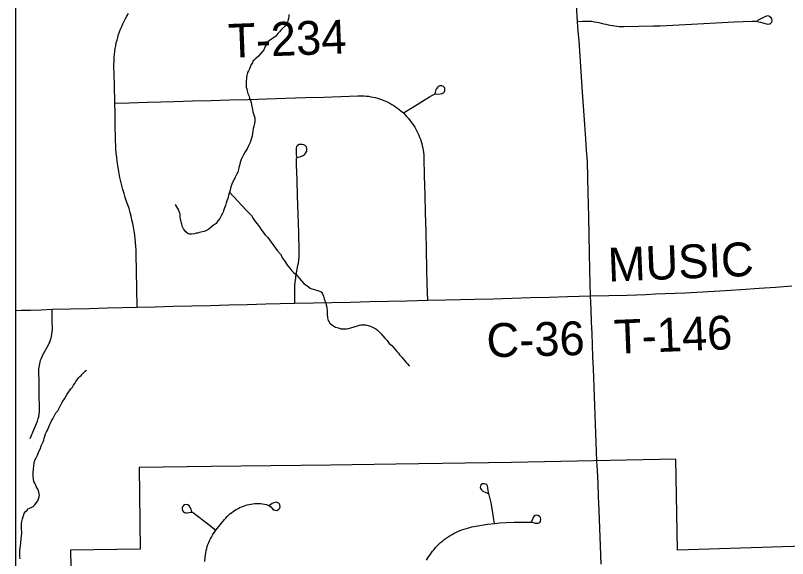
# Model space of a CAD drawing. Extents: x 103424 to 286016, y 38711 to 110967.
# Drawn here: x 103424 to 110306, y 48305 to 53149 of the extents above; entities that cross this region are included whole.
import ezdxf

# ---------------------------------------------------------------- set-up
doc = ezdxf.new("R2010")
doc.units = 0
for name, color, linetype in [('GM_X_City_Street', 7, 'Continuous'), ('GM_X_Corporation', 7, 'Continuous'), ('GM_X_County_Road_Text', 7, 'Continuous'), ('GM_X_Minor_River', 7, 'Continuous'), ('GM_X_State_Route', 7, 'Continuous'), ('GM_X_Township_Road', 7, 'Continuous'), ('GM_X_Township_Road_Text', 7, 'Continuous')]:
    doc.layers.add(name, color=color, linetype=linetype)

msp = doc.modelspace()

# ---------------------------------------------------------------- linework, layer by layer
at = {"layer": 'GM_X_City_Street'}
for points in [[(107692.3, 48618.7), (107685.6, 48672.4), (107676.2, 48734.3), (107664.8, 48802.2), (107649.9, 48861.2), (107637.5, 48910.2), (107633.7, 48937.3), (107630.2, 48951.9), (107624.2, 48962.1), (107615.1, 48968.2), (107602.4, 48971.2), (107587.9, 48970.6), (107573.3, 48961.5), (107567.9, 48951.2), (107566.7, 48939.8), (107569.7, 48929.5), (107576.4, 48917), (107589.1, 48907.1), (107604, 48899.7), (107638.2, 48886.1)], [(105113, 48278.3), (105114.5, 48316.9), (105116.3, 48332.3), (105120.3, 48359), (105124.1, 48377.1), (105128.4, 48394.9), (105133.7, 48412.6), (105139.5, 48430.1), (105146, 48447.2), (105153.3, 48464.1), (105161.4, 48480.6), (105170, 48496.9), (105179.3, 48512.7), (105189.4, 48528.2), (105199.9, 48543.2), (105211.3, 48557.8), (105287.1, 48652.4), (105298.2, 48665.7), (105310.3, 48678.6), (105322.6, 48690.9), (105335.4, 48702.7), (105349, 48713.8), (105362.9, 48724.3), (105377.5, 48734.1), (105392.3, 48743.3), (105407.5, 48751.8), (105423.1, 48759.6), (105439.2, 48766.6), (105455.3, 48772.9), (105471.9, 48778.5), (105488.8, 48783.3), (105505.6, 48787.3), (105522.7, 48790.6), (105540.1, 48793), (105557.5, 48794.7), (105574.9, 48795.6), (105609.6, 48795), (105627, 48793.5), (105644.3, 48791.2), (105661.5, 48788.1), (105683.6, 48777.6), (105699.8, 48765.9), (105714.9, 48749.3), (105726.2, 48739.9), (105736.3, 48735.4), (105747.7, 48733.7), (105760.8, 48737.7), (105772.2, 48744.8), (105780.4, 48755.7), (105783.9, 48769.2), (105780.8, 48783.6), (105774, 48795.3), (105763.9, 48802.9), (105751.4, 48806.6), (105725.4, 48802.5), (105712.2, 48794.6), (105688.9, 48779.1)], [(104995.6, 48722.3), (104986.1, 48750.4), (104980.6, 48764), (104972.4, 48775.4), (104960.2, 48784), (104943.3, 48785.6), (104931.5, 48782.9), (104921.4, 48776.9), (104913.1, 48767.1), (104909.3, 48756.9), (104909.7, 48744.9), (104913.8, 48733.2), (104921, 48722.6), (104930.8, 48715.5), (104942.5, 48712.1), (104954.2, 48711.3), (104971.5, 48716.3), (104985.8, 48719.3), (104997.9, 48718.5), (105010.7, 48712.5), (105037.8, 48692.9), (105124.5, 48625.4), (105211.3, 48557.8)], [(107088.5, 48291.6), (107104.8, 48318.8), (107116.4, 48336.4), (107128.5, 48353.6), (107141.4, 48370.3), (107154.7, 48386.7), (107168.5, 48402.5), (107183.2, 48417.8), (107198, 48432.6), (107213.6, 48446.9), (107229.7, 48460.6), (107246.1, 48473.8), (107263, 48486.4), (107280.4, 48498.3), (107298.2, 48509.7), (107316.4, 48520.5), (107334.8, 48530.6), (107353.6, 48540), (107372.8, 48548.8), (107392.4, 48556.9), (107412, 48564.3), (107431.9, 48571.1), (107452.3, 48577.1), (107472.7, 48582.4), (107493.1, 48587), (107527.6, 48593.9), (107562.3, 48600), (107597.1, 48605.6), (107631.8, 48610.5), (107692.3, 48618.7), (107742.5, 48624.1), (107798.8, 48627.5), (107867.8, 48628.8), (107943.5, 48630.1), (108030, 48628.1), (108054.9, 48622), (108068.9, 48619.3), (108084.2, 48620.3), (108097.8, 48627.5), (108103.9, 48635.6), (108107.3, 48653), (108102.5, 48670), (108094.7, 48680.9), (108080.8, 48689.1), (108067.4, 48690.5), (108055, 48687.5), (108045.2, 48681.1), (108038, 48670.5), (108032, 48654.7), (108020.7, 48631.7)]]:
    msp.add_lwpolyline(points, dxfattribs=at)
at = {"layer": 'GM_X_Corporation'}
msp.add_lwpolyline([(103423.7, 96534.8), (103423.7, 38711.2), (175679.7, 38711.2), (175679.7, 110967.2), (119699, 110967.2), (119716.9, 106542.5), (119719.8, 106322.8), (119720.8, 106006.3), (119709.7, 99445.7), (119706.4, 99064.2), (119663.9, 96690), (117026.4, 96688.2), (115542.1, 96665), (105081.7, 96574.5)], close=True, dxfattribs=at)
for points in [[(103423.7, 70904.9), (103423.7, 43132.7), (108691.3, 43264.4), (116952, 43470.9), (119934.2, 43543), (119908.2, 46302.1), (119859.8, 51426.6), (119800.4, 57496.9), (119747.3, 63220.6), (119711.4, 67089.1)], [(117498.8, 48671.3), (116838, 48636.4), (116311.9, 48611.3), (115744, 48584.2), (115283.9, 48565.5), (114959.7, 48555.3), (113527.1, 48511.6), (111482.4, 48447.7), (109323.7, 48380.3), (109308.9, 49192.1), (107845.9, 49162.1), (106813.4, 49147.1), (106231.9, 49138.7), (105167.6, 49124.8), (104527.8, 49118.1), (104535.3, 48390), (103915.8, 48379.3), (103918.7, 48227.5)]]:
    msp.add_lwpolyline(points, dxfattribs=at)
at = {"layer": 'GM_X_Minor_River'}
for points in [[(105859.7, 53158.7), (105860, 53140.6), (105858.3, 53122.4), (105854.4, 53112.2), (105852.6, 53100), (105848.8, 53087.8), (105837, 53069.5), (105825.1, 53053.1), (105807.3, 53034.6), (105789.4, 53018.2), (105777.5, 53003.8), (105763.7, 52987.5), (105745.9, 52964.9), (105723.9, 52950.4), (105712, 52940.1), (105698, 52931.8), (105686, 52923.5), (105674.1, 52913.3), (105664.2, 52901), (105658.4, 52886.7), (105650.6, 52872.5), (105644.8, 52858.2), (105637, 52841.9), (105623.1, 52823.5), (105605.3, 52805.1), (105589.5, 52784.6), (105567.6, 52764), (105553.7, 52751.7), (105539.8, 52741.3), (105538, 52725.2), (105524.1, 52712.8), (105508.6, 52674.2), (105500.9, 52653.8), (105493.1, 52639.6), (105489.3, 52625.4), (105485.4, 52613.2), (105483.7, 52599), (105481.9, 52584.8), (105480.2, 52564.6), (105480.5, 52544.4), (105480.8, 52526.2), (105481.1, 52508.1), (105485.4, 52492), (105489.8, 52475.9), (105496.2, 52453.8), (105504.6, 52433.7), (105511, 52411.6), (105519.4, 52391.5), (105523.8, 52371.4), (105528.2, 52351.3), (105534.7, 52325.1), (105539.3, 52290.8), (105547.8, 52262.7), (105554.2, 52244.6), (105558.4, 52234.6), (105558.6, 52220.4), (105556.9, 52200.2), (105553.2, 52184), (105547.5, 52161.7), (105543.8, 52139.4), (105540.2, 52117.1), (105536.5, 52096.9), (105532.8, 52076.6), (105527.1, 52054.3), (105521.3, 52038), (105517.6, 52021.8), (105509.8, 52003.5)], [(105509.8, 52003.5), (105502, 51987.2), (105488.3, 51960.7), (105470.7, 51932.1), (105455, 51905.6), (105443.2, 51883.2), (105435.5, 51862.9), (105427.9, 51836.5), (105420.2, 51810.1), (105414.5, 51793.9), (105410.7, 51775.6), (105405.1, 51751.3), (105393.3, 51730.9), (105383.6, 51706.5), (105352.4, 51645.4), (105344.8, 51619), (105337.2, 51590.6), (105329.5, 51564.2), (105323.8, 51543.9), (105320, 51531.7), (105316.2, 51517.5), (105306.5, 51495.1), (105300.7, 51476.8), (105295.1, 51454.5), (105287.4, 51432.2), (105281.6, 51415.9), (105277.7, 51405.7), (105273.9, 51393.6), (105268, 51381.3), (105258.3, 51361), (105244.5, 51338.5), (105228.7, 51318.1), (105213, 51293.6), (105187.1, 51275), (105169.2, 51260.5), (105147.3, 51242), (105121.3, 51227.4), (105103.2, 51221.1), (105091.2, 51218.8), (105077.1, 51214.6), (105063, 51212.3), (105049, 51208.1), (105034.9, 51205.8), (105018.8, 51201.5), (104996.7, 51197.1), (104986.6, 51196.9), (104974.5, 51198.8), (104962.3, 51200.6), (104943.8, 51220.5), (104929.5, 51234.4), (104921.2, 51246.4), (104912.8, 51264.4), (104906.4, 51288.5), (104902, 51306.6), (104897.7, 51322.7), (104895.5, 51332.8), (104893.2, 51350.9), (104891, 51361), (104890.8, 51375.1), (104888.6, 51385.2), (104884.3, 51399.3), (104880, 51413.4), (104853.1, 51457.3), (104846.9, 51463.3)], [(105331.9, 51572.2), (105481.4, 51411.1), (105504, 51389.3), (105526.6, 51365.4), (105543.2, 51339.4), (105561.8, 51311.4), (105578.3, 51289.5), (105596.9, 51267.6), (105611.4, 51243.6), (105628, 51217.6), (105648.6, 51191.7), (105673.2, 51167.8), (105757.9, 51052), (105786.7, 51020.2), (105807.5, 50982.2), (105828.2, 50950.2), (105848.9, 50920.2), (105869.5, 50894.3), (105888.1, 50872.4), (105906.5, 50854.5), (105924.9, 50838.6), (105941.4, 50820.7), (105955.8, 50802.8), (105972.3, 50780.8), (105994.9, 50757), (106009.2, 50747.1), (106021.4, 50739.2), (106035.8, 50727.3), (106050.1, 50715.4), (106064.3, 50709.6), (106080.5, 50707.9), (106090.7, 50704), (106104.9, 50700.2), (106119.1, 50694.4), (106133.3, 50688.5), (106149.5, 50684.8), (106161.9, 50664.8), (106168.3, 50646.7), (106176.8, 50620.6), (106185.3, 50598.5), (106191.6, 50580.4), (106196, 50560.3), (106198.4, 50538.1), (106200.8, 50513.9), (106201.3, 50485.6), (106205.9, 50451.4), (106212.3, 50429.2), (106220.6, 50415.2), (106226.9, 50405.2), (106243.3, 50389.3), (106257.6, 50379.5), (106277.9, 50369.7), (106302.2, 50362), (106324.6, 50354.3), (106342.8, 50352.6), (106358.9, 50352.9), (106375, 50355.1), (106391.1, 50357.4), (106413.2, 50363.9), (106473.5, 50381), (106489.5, 50385.3), (106503.6, 50389.6), (106517.7, 50389.8), (106531.8, 50390), (106548, 50388.3), (106568.3, 50382.6), (106584.5, 50378.8), (106600.8, 50371), (106617, 50363.2), (106635.4, 50353.4), (106649.7, 50341.5), (106666.1, 50327.6), (106682.5, 50309.7), (106698.9, 50291.8), (106717.4, 50271.9), (106736, 50250), (106754.6, 50224), (106779.1, 50206.2), (106793.6, 50186.3), (106808, 50168.3), (106822.4, 50152.4), (106836.8, 50136.5), (106847.1, 50122.5), (106859.4, 50110.6), (106867.6, 50100.6), (106882.1, 50082.7), (106892.4, 50070.7), (106906.8, 50052.8), (106919.1, 50040.9), (106931.4, 50026.9), (106937.5, 50025)], [(103465.4, 48303.3), (103463, 48325.5), (103462.6, 48349.8), (103464.1, 48382.1), (103467.6, 48414.5), (103471.1, 48444.8), (103474.5, 48483.3), (103478.1, 48507.6), (103479.7, 48529.8), (103481.4, 48550.1), (103479.2, 48562.1), (103479, 48572.2), (103476.7, 48588.4), (103476.4, 48606.5), (103478.2, 48618.7), (103482, 48634.9), (103487.6, 48659.2), (103493.4, 48679.5), (103497.1, 48693.7), (103501, 48705.9), (103510.8, 48720.2), (103528.7, 48736.7), (103538.6, 48746.9), (103552.7, 48753.2), (103564.6, 48761.5), (103580.6, 48769.8), (103592.5, 48782.2), (103622.1, 48821), (103629.9, 48837.3), (103635.7, 48855.6), (103637.5, 48869.8), (103635.2, 48881.9), (103633, 48896), (103628.7, 48912), (103618.2, 48932.1), (103609.9, 48948.1), (103601.6, 48964.1), (103595.3, 48976.1), (103589, 48992.2), (103584.6, 49014.4), (103582.1, 49040.6), (103581.6, 49070.9), (103585.1, 49101.2), (103586.6, 49131.5), (103590.3, 49155.9), (103597.9, 49182.2), (103607.6, 49202.6), (103617.4, 49220.9), (103629, 49251.4), (103646.5, 49290.1), (103654.2, 49310.4), (103669.8, 49345), (103675.6, 49361.3), (103679.3, 49377.5), (103687.1, 49397.8), (103692.8, 49416.1), (103700.6, 49434.4), (103708.4, 49450.7), (103716.2, 49465), (103722, 49479.2), (103727.8, 49495.5), (103735.6, 49513.8), (103745.3, 49532.1), (103757.1, 49552.5), (103768.8, 49574.9), (103782.5, 49603.4), (103800.3, 49623.9), (103812, 49646.3), (103823.8, 49664.7), (103835.6, 49687.1), (103847.3, 49707.5), (103861.1, 49730), (103872.8, 49750.4), (103884.6, 49770.8), (103918.1, 49817.8), (103932, 49834.2), (103941.7, 49852.5), (103953.6, 49866.9), (103963.4, 49883.2), (103973.2, 49899.5), (103987.1, 49915.9), (103999, 49928.2), (104008.9, 49938.5), (104018.8, 49948.7), (104034.7, 49963.1), (104044.6, 49977.4), (104056.5, 49985.7)]]:
    msp.add_lwpolyline(points, dxfattribs=at)
at = {"layer": 'GM_X_State_Route'}
for points in [[(108607.1, 49174.6), (108600.7, 49339.6), (108594.4, 49504.5), (108588, 49669.4), (108581.6, 49834.4), (108575.3, 49999.3), (108571.2, 50105), (108567.1, 50210.8), (108563.3, 50311.8), (108559.5, 50412.8), (108554.7, 50530), (108549.7, 50647.2), (108547.3, 50762.4), (108544.9, 50877.5), (108541.5, 51032.8), (108538.2, 51188.1), (108533.6, 51353.1), (108530.5, 51460.5), (108527.5, 51567.8), (108524.4, 51707.5), (108521.3, 51847.3), (108513.9, 51947.7), (108506.6, 52048), (108498.1, 52174), (108489.7, 52300), (108478.6, 52464.7), (108472.3, 52557.2), (108466.1, 52649.8), (108456.5, 52785.7), (108446.9, 52921.7), (108440.7, 53007.9), (108434.5, 53093.9), (108424.3, 53243.5)], [(108644.6, 48254.5), (108638.8, 48419.5), (108633.2, 48576.4), (108627.6, 48733.3), (108621.7, 48857.1), (108617.1, 48973.6), (108612.6, 49090), (108607.1, 49174.6)]]:
    msp.add_lwpolyline(points, dxfattribs=at)
at = {"layer": 'GM_X_Township_Road'}
for points in [[(104509.2, 50547.2), (104506.3, 50712.2), (104503.6, 50866.8), (104500.8, 51021.3), (104499.6, 51055.5), (104497.6, 51089.7), (104494.8, 51123.8), (104491.3, 51157.9), (104487.1, 51191.9), (104482, 51225.7), (104476.3, 51259.4), (104469.7, 51293.1), (104462.4, 51326.5), (104454.4, 51359.8), (104445.6, 51392.9), (104436.3, 51425.8), (104426, 51458.5), (104414.9, 51490.9), (104403.1, 51525.6), (104392.3, 51560.5), (104382, 51595.6), (104372.2, 51631), (104363.4, 51666.5), (104355.4, 51702.2), (104348.1, 51738.1), (104341.6, 51774.1), (104335.8, 51810.3), (104330.5, 51846.5), (104326.3, 51882.9), (104322.8, 51919.3), (104320, 51955.8), (104318, 51992.4), (104316.7, 52028.9), (104313.7, 52194), (104312.2, 52280.6), (104310.6, 52367.3), (104306.4, 52532.3), (104304.3, 52615.5), (104302.2, 52698.7), (104302.7, 52750.4), (104304, 52776.2), (104306.3, 52801.9), (104309.1, 52827.6), (104312.8, 52853.2), (104317.4, 52878.6), (104322.7, 52903.9), (104329, 52928.9), (104335.8, 52953.8), (104343.4, 52978.5), (104351.9, 53002.9), (104361, 53027.1), (104370.8, 53050.9), (104381.6, 53074.5), (104393, 53097.7), (104405.1, 53120.5), (104417.7, 53143), (104431.3, 53165)], [(108434.5, 53093.9), (108477.9, 53097.7), (108498.7, 53098.8), (108519.6, 53099.1), (108540.8, 53098.6), (108561.7, 53097.4), (108584.4, 53093.4), (108606.5, 53088), (108623.3, 53084.7), (108644.8, 53079.3), (108666.9, 53074.6), (108686.3, 53069.9), (108707.1, 53065.9), (108726, 53062.5), (108744.6, 53059.4), (108764.8, 53055.9), (108784.9, 53053.1), (108805.3, 53051.1), (108825.7, 53049.8), (108846.1, 53049.2), (108978.7, 53052.3), (109111.4, 53055.3), (109169.1, 53056.9), (109226.7, 53059.2), (109284.3, 53061.9), (109449.2, 53070.6), (109559, 53076.5), (109668.8, 53082.3), (109829, 53090.7), (109989.1, 53099.2), (110023.2, 53097.8), (110065, 53089.3), (110086.4, 53083), (110095.6, 53080), (110117.1, 53074.7), (110127.8, 53072), (110143, 53073.2), (110150.3, 53075.1), (110154.7, 53078.2), (110160, 53082.7), (110163.1, 53086.8), (110167.6, 53096.9), (110168.1, 53106.9), (110164.6, 53120), (110159.2, 53129.2), (110149, 53137.1), (110139, 53142.6), (110129.9, 53144.2), (110109.8, 53141.1), (110098.2, 53135.1), (110084.1, 53127.7), (110061.6, 53115.8), (110032.7, 53101.9)], [(106882.1, 52279.1), (106979.6, 52339.6), (107077.1, 52400.2), (107115.5, 52423.8), (107135.8, 52436.3), (107151.5, 52445), (107166.2, 52448.9), (107180.6, 52448.1), (107210.7, 52449.5), (107227.2, 52452.4), (107237.2, 52457.4), (107245.5, 52465.9), (107250.3, 52475.8), (107252.3, 52482.3), (107251.6, 52496.8), (107247.9, 52505.5), (107239.4, 52515.3), (107232.8, 52518.4), (107224.1, 52520.8), (107218.2, 52521.9), (107207.7, 52521), (107199.8, 52518.2), (107191.3, 52512.1), (107182.3, 52503.8), (107176.2, 52495.3), (107171.9, 52487.6), (107168.3, 52476.4), (107160.9, 52449.1)], [(104310.6, 52367.3), (104436.5, 52369.6), (104601.5, 52374.6), (104719.8, 52378.1), (104838.1, 52381.6), (105003.1, 52386.2), (105168.1, 52390.8), (105333.1, 52395.5), (105498.1, 52400), (105581.9, 52402.4), (105665.7, 52404.7), (105830.7, 52410.2), (105919.7, 52413.2), (106008.8, 52416.2), (106173.7, 52421.5), (106325, 52426.3), (106476.2, 52431.2), (106531.5, 52432), (106551.7, 52430.2), (106571.5, 52427.7), (106591.2, 52424.5), (106610.8, 52420.7), (106630.4, 52416.2), (106649.8, 52410.9), (106669, 52405.1), (106687.8, 52398.5), (106706.5, 52391.3), (106724.8, 52383.4), (106742.9, 52374.9), (106760.8, 52365.8), (106778.4, 52356), (106795.5, 52345.6), (106812.4, 52334.7), (106828.7, 52323.2), (106844.6, 52311.1), (106860.2, 52298.5), (106882.1, 52279.1), (106896.4, 52263.1), (106910.5, 52248.7), (106923.8, 52233.8), (106936.7, 52218.4), (106949, 52202.7), (106960.9, 52186.4), (106971.9, 52169.8), (106982.7, 52152.8), (106992.5, 52135.4), (107002.1, 52117.8), (107010.9, 52099.8), (107018.9, 52081.5), (107026.5, 52062.9), (107033.3, 52044.1), (107039.6, 52025), (107045.1, 52005.7), (107049.9, 51986.3), (107053.9, 51966.7), (107057.4, 51947), (107060.2, 51927.1), (107062.4, 51907.2), (107063.9, 51881.5), (107068, 51716.5), (107072, 51551.5), (107076.1, 51386.5), (107080.2, 51221.5), (107084.2, 51056.5), (107088.3, 50891.6), (107091.8, 50750), (107095.3, 50608.5)], [(105914.5, 50581.9), (105912.8, 50665.5), (105913.3, 50720.1), (105914, 50733.7), (105915.1, 50747.3), (105916.3, 50761), (105917.8, 50774.5), (105919.6, 50788.1), (105921.6, 50801.7), (105924.4, 50819.3), (105942.1, 50919.4), (105945.3, 50939.9), (105948.9, 50966.5), (105951.4, 50993.1), (105953.2, 51019.7), (105953.7, 51046.5), (105948.5, 51211.5), (105943.3, 51376.5), (105938.1, 51541.5), (105933.8, 51678.9), (105929.5, 51816.4), (105929, 51844.3), (105929.7, 51875.4), (105930.2, 51878.3), (105932.2, 51879.9), (105935, 51880.8), (105945.4, 51884.2), (105967.2, 51891.1), (105988.4, 51900.2), (106003.1, 51911.9), (106012.9, 51922.3), (106021, 51939.8), (106021.8, 51958.5), (106016.7, 51977.2), (106007, 51989), (105994.9, 51995.2), (105978.2, 51999.1), (105951.3, 51996.8), (105938.5, 51988.8), (105930, 51979.3), (105926.4, 51968.2), (105925.1, 51948.9), (105926.7, 51902.8), (105930.8, 51880.5)], [(103423.7, 50518.6), (103473.4, 50519.8), (103558.5, 50521.7), (103654.3, 50524.8), (103750.2, 50527.9), (103915.2, 50532.1), (104080.2, 50536.3), (104245.2, 50540.5), (104377.2, 50543.8), (104509.2, 50547.2), (104669.5, 50551.2), (104829.8, 50555.1), (104994.8, 50559.2), (105159.8, 50563.2), (105324.8, 50567.3), (105489.8, 50571.4), (105654.8, 50575.5), (105784.6, 50578.7), (105914.5, 50581.9), (106079.5, 50585.6), (106244.5, 50589.3), (106409.6, 50593), (106496.6, 50595), (106583.5, 50596.9), (106748.6, 50600.7), (106913.6, 50604.4), (107004.4, 50606.5), (107095.3, 50608.5), (107260.3, 50612.2), (107390, 50615.1), (107519.7, 50618), (107684.7, 50622.7), (107849.7, 50627.4), (108014.7, 50632.1), (108179.7, 50636.8), (108344.7, 50641.4), (108447.2, 50644.3), (108549.7, 50647.2), (108713.6, 50651), (108877.4, 50654.6), (109042.3, 50661.2), (109130, 50664.7), (109217.6, 50668.2), (109304.8, 50671.2), (109392, 50674.3), (109547.4, 50683.5), (109702.8, 50692.7), (109796.1, 50698.3), (109889.5, 50703.8), (110054.1, 50716), (110199.6, 50726.9), (110345.2, 50737.7)], [(103556.2, 49375.9), (103587.6, 49452.4), (103619, 49528.9), (103627.3, 49553.9), (103631.3, 49569.3), (103636.1, 49595.2), (103637.9, 49610.9), (103638.9, 49626.7), (103635.9, 49791.7), (103634.4, 49882), (103632.7, 49972.3), (103633.3, 49995.7), (103634.8, 50011.4), (103636.8, 50027.1), (103639.8, 50042.6), (103643.6, 50058), (103648.2, 50073.2), (103655.5, 50092.9), (103662, 50107.4), (103669.1, 50121.5), (103716.9, 50210.1), (103725.5, 50227.4), (103731.8, 50241.9), (103737.4, 50256.7), (103741.9, 50271.8), (103745.9, 50287.2), (103749, 50302.7), (103752.2, 50328.8), (103753.2, 50344.6), (103751.7, 50436.2), (103750.2, 50527.9)]]:
    msp.add_lwpolyline(points, dxfattribs=at)

# ---------------------------------------------------------------- texts
at = {"layer": 'GM_X_County_Road_Text'}
msp.add_text('C-36', height=301.87, rotation=1.37265, dxfattribs=at).set_placement((107625.9, 50099.8))
at = {"layer": 'GM_X_Township_Road_Text'}
for s, rotation, p in [('T-234', 2.19044, (105325, 52770.6)), ('MUSIC', 2.34173, (108709.6, 50774)), ('T-146', 2.25063, (108764.3, 50131.4))]:
    msp.add_text(s, height=301.87, rotation=rotation, dxfattribs=at).set_placement(p)

doc.saveas('drawing.dxf')
